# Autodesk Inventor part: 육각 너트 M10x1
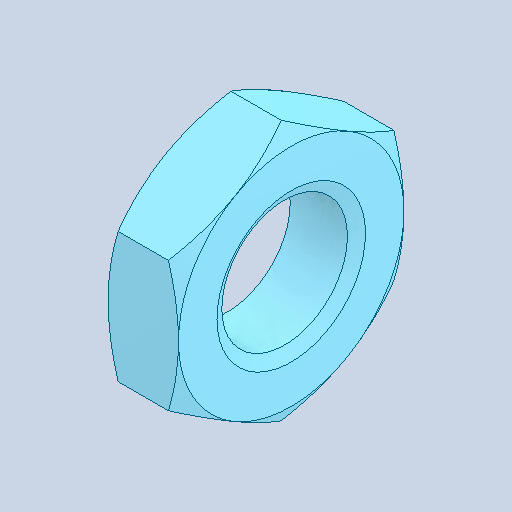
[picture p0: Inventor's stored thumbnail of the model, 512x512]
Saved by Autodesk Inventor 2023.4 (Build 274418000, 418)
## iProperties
Created: 2024-09
Part Number: 육각 너트 M10x1
Material: 강철, 연강
Description: 6각 너트 및 6각 가는 너트 - 이중 모따기
Document SubType Name: Modeling
Designer: EDU
Density: 7.85 g/cm^3
Appearance: 기본값
Author: jhkim
Sending System: Autodesk Inventor 2025
Preprocessor: ST-DEVELOPER v20
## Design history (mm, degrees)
feature "Solid1"
node "솔리드1"
